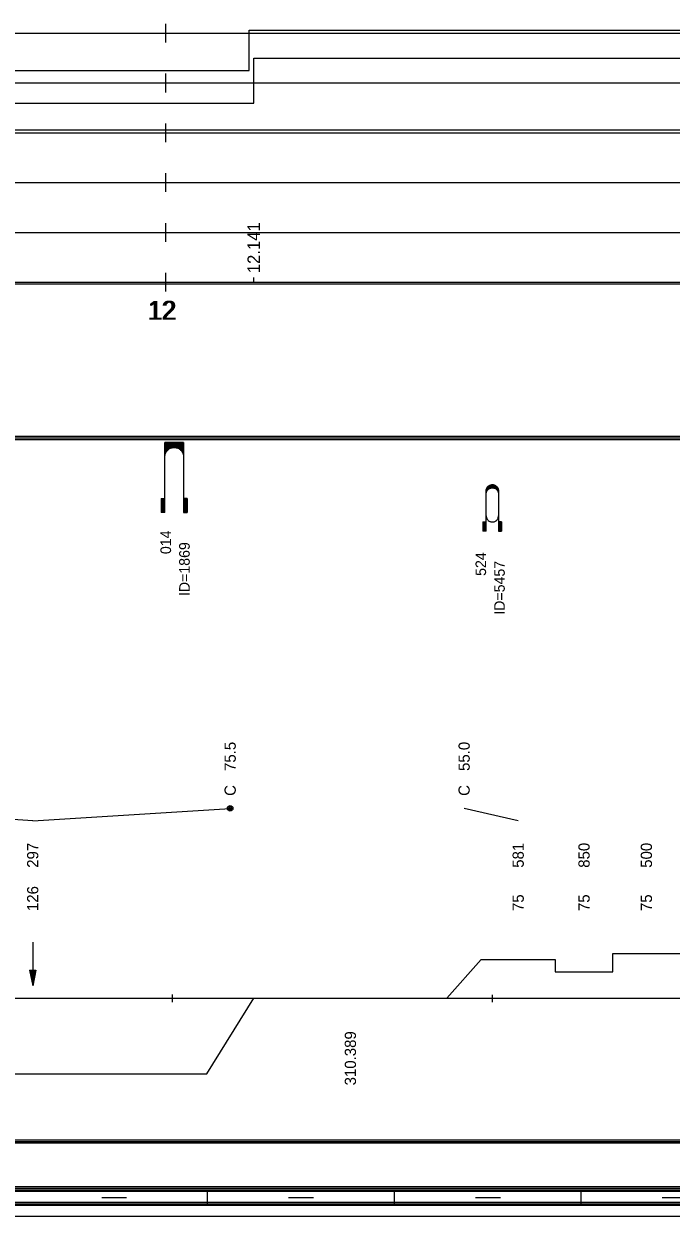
# Model space of a CAD drawing. Extents: x 2 to 10148, y 0 to 380.
# Drawn here: x 1475.5 to 1579.4, y 0 to 191.5 of the extents above; entities that cross this region are included whole.
import ezdxf

# ---------------------------------------------------------------- set-up
doc = ezdxf.new("R2010")
doc.units = 0
for name, color, linetype in [('CARA_S_OBJEKTY', 7, 'Continuous'), ('KRIV1_CARA', 7, 'Continuous'), ('KRIV1_TEXT', 7, 'Continuous'), ('OBJEKTY_TEXT', 7, 'Continuous'), ('OBJEKTY_TVAR', 7, 'Continuous'), ('RAM', 7, 'Continuous'), ('RYCHL_A', 7, 'Continuous'), ('RYCHL_B', 7, 'Continuous'), ('RYCHL_C', 7, 'Continuous'), ('RYCHL_RASTR', 7, 'Continuous'), ('RYCHL_STAN', 7, 'Continuous'), ('STAN_CARA', 7, 'Continuous'), ('STANIC_ZMEN_V', 7, 'Continuous')]:
    doc.layers.add(name, color=color, linetype=linetype)

msp = doc.modelspace()

# ---------------------------------------------------------------- linework, layer by layer
for p, q in [((1499.33, 35.58), (1499.33, 34.39)), ((1550.68, 35.56), (1550.68, 34.37))]:
    msp.add_line(p, q)
at = {"layer": 'CARA_S_OBJEKTY'}
for p, q in [((1245.39, 125.25), (1850.83, 125.25)), ((1245.39, 125), (1850.83, 125)), ((1245.39, 124.75), (1850.83, 124.75))]:
    msp.add_line(p, q, dxfattribs=at)
at = {"layer": 'KRIV1_CARA'}
for p, q in [((1570.07, 39.24), (1570.07, 42.2)), ((1570.07, 42.2), (1580.8, 42.2)), ((1543.43, 35), (1548.93, 41.2)), ((1548.93, 41.2), (1560.78, 41.2)), ((1560.78, 41.2), (1560.78, 39.24)), ((1560.78, 39.24), (1570.07, 39.24)), ((1245.39, 35), (1850.83, 35)), ((1504.85, 22.86), (1512.4, 35)), ((1449, 22.86), (1504.85, 22.86))]:
    msp.add_line(p, q, dxfattribs=at)
at = {"layer": 'KRIV1_TEXT'}
for p, q in [((1476.92, 63.5), (1444.03, 65.5)), ((1476.92, 63.5), (1508.62, 65.5)), ((1554.86, 63.5), (1546.18, 65.5)), ((1476.92, 44), (1476.92, 42.2)), ((1476.92, 42.2), (1476.92, 40)), ((1476.42, 39.5), (1476.92, 37)), ((1476.42, 39.5), (1477.42, 39.5)), ((1476.52, 39.5), (1476.92, 37.5)), ((1476.62, 39.5), (1476.92, 38)), ((1476.72, 39.5), (1476.92, 38.5)), ((1476.82, 39.5), (1476.92, 39)), ((1476.92, 40), (1476.92, 37)), ((1477.42, 39.5), (1476.92, 37)), ((1477.32, 39.5), (1476.92, 37.5)), ((1477.22, 39.5), (1476.92, 38)), ((1477.12, 39.5), (1476.92, 38.5)), ((1477.02, 39.5), (1476.92, 39)), ((1476.92, 39.5), (1476.92, 39.5)), ((1476.92, 39.5), (1476.92, 39.5))]:
    msp.add_line(p, q, dxfattribs=at)
for radius in [0.45, 0.3, 0.15]:
    msp.add_circle((1508.62, 65.5), radius, dxfattribs=at)
at = {"layer": 'OBJEKTY_TVAR'}
for p, q in [((1498.13, 113), (1498.13, 124.25)), ((1501.13, 124.25), (1498.13, 124.25)), ((1498.13, 124.17), (1501.13, 124.17)), ((1498.13, 124.1), (1501.13, 124.1)), ((1498.13, 124.02), (1501.13, 124.02)), ((1498.13, 123.95), (1501.13, 123.95)), ((1498.13, 123.87), (1501.13, 123.87)), ((1498.13, 123.8), (1501.13, 123.8)), ((1498.13, 123.72), (1501.13, 123.72)), ((1498.13, 123.65), (1501.13, 123.65)), ((1498.13, 123.57), (1501.13, 123.57)), ((1498.13, 123.5), (1501.13, 123.5)), ((1498.13, 123.42), (1499.29, 123.42)), ((1498.13, 123.35), (1499.05, 123.35)), ((1498.13, 123.27), (1498.9, 123.27)), ((1498.13, 123.2), (1498.78, 123.2)), ((1498.13, 123.12), (1498.68, 123.12)), ((1498.13, 123.05), (1498.59, 123.05)), ((1498.13, 122.97), (1498.52, 122.97)), ((1498.13, 122.9), (1498.46, 122.9)), ((1498.13, 122.82), (1498.4, 122.82)), ((1498.13, 122.75), (1498.35, 122.75)), ((1498.13, 122.67), (1498.31, 122.67)), ((1498.13, 122.6), (1498.27, 122.6)), ((1498.21, 122.46), (1498.28, 122.61)), ((1498.28, 122.61), (1498.35, 122.75)), ((1498.35, 122.75), (1498.46, 122.9)), ((1498.46, 122.9), (1498.59, 123.05)), ((1498.59, 123.05), (1498.67, 123.12)), ((1498.67, 123.12), (1498.77, 123.19)), ((1498.77, 123.19), (1498.9, 123.27)), ((1498.9, 123.27), (1499.05, 123.35)), ((1499.05, 123.35), (1499.29, 123.42)), ((1499.29, 123.42), (1499.5, 123.46)), ((1499.5, 123.46), (1499.75, 123.46)), ((1499.75, 123.46), (1499.89, 123.44)), ((1499.89, 123.44), (1499.97, 123.42)), ((1499.97, 123.42), (1501.13, 123.42)), ((1499.97, 123.42), (1500.21, 123.35)), ((1500.21, 123.35), (1501.13, 123.35)), ((1500.21, 123.35), (1500.36, 123.27)), ((1500.36, 123.27), (1501.13, 123.27)), ((1500.36, 123.27), (1500.48, 123.2)), ((1500.48, 123.2), (1501.13, 123.2)), ((1500.48, 123.2), (1500.58, 123.12)), ((1500.58, 123.12), (1501.13, 123.12)), ((1500.58, 123.12), (1500.67, 123.05)), ((1500.67, 123.05), (1501.13, 123.05)), ((1500.67, 123.05), (1500.74, 122.97)), ((1500.74, 122.97), (1501.13, 122.97)), ((1500.74, 122.97), (1500.8, 122.9)), ((1500.8, 122.9), (1501.12, 122.9)), ((1500.8, 122.9), (1500.86, 122.82)), ((1500.86, 122.82), (1501.13, 122.82)), ((1500.86, 122.82), (1500.95, 122.67)), ((1500.91, 122.75), (1501.13, 122.75)), ((1500.95, 122.67), (1501.13, 122.67)), ((1500.95, 122.67), (1501.02, 122.52)), ((1500.99, 122.6), (1501.13, 122.6)), ((1501.13, 124.25), (1501.13, 113)), ((1498.13, 122.52), (1498.24, 122.52)), ((1498.13, 122.45), (1498.21, 122.45)), ((1498.13, 122.37), (1498.19, 122.37)), ((1498.13, 122.3), (1498.17, 122.3)), ((1498.13, 122.22), (1498.15, 122.22)), ((1498.13, 122.15), (1498.14, 122.15)), ((1498.13, 121.97), (1498.14, 122.11)), ((1498.14, 122.11), (1498.16, 122.28)), ((1498.16, 122.28), (1498.21, 122.46)), ((1501.02, 122.52), (1501.13, 122.52)), ((1501.02, 122.52), (1501.07, 122.37)), ((1501.05, 122.45), (1501.13, 122.45)), ((1501.07, 122.37), (1501.13, 122.37)), ((1501.07, 122.37), (1501.11, 122.22)), ((1501.09, 122.3), (1501.13, 122.3)), ((1501.11, 122.22), (1501.13, 122.22)), ((1501.11, 122.22), (1501.13, 121.97)), ((1501.12, 122.15), (1501.13, 122.15)), ((1549.76, 116.81), (1549.82, 116.95)), ((1549.77, 116.85), (1550.22, 116.85)), ((1549.79, 116.9), (1550.33, 116.9)), ((1549.82, 116.95), (1549.88, 117.06)), ((1549.82, 116.95), (1550.48, 116.95)), ((1549.84, 117), (1551.58, 117)), ((1549.87, 117.05), (1551.55, 117.05)), ((1549.88, 117.06), (1549.97, 117.18)), ((1549.91, 117.1), (1551.51, 117.1)), ((1549.95, 117.15), (1551.47, 117.15)), ((1549.97, 117.18), (1550.06, 117.26)), ((1550, 117.2), (1551.42, 117.2)), ((1550.05, 117.25), (1551.37, 117.25)), ((1550.06, 117.26), (1550.19, 117.35)), ((1550.06, 116.74), (1550.19, 116.83)), ((1550.11, 117.3), (1551.31, 117.3)), ((1550.18, 117.35), (1551.24, 117.35)), ((1550.19, 117.35), (1550.32, 117.42)), ((1550.19, 116.83), (1550.32, 116.9)), ((1550.27, 117.4), (1551.15, 117.4)), ((1550.32, 117.42), (1550.35, 117.43)), ((1550.32, 116.9), (1550.35, 116.91)), ((1550.35, 117.43), (1550.47, 117.47)), ((1550.35, 116.91), (1550.47, 116.95)), ((1550.4, 117.45), (1551.02, 117.45)), ((1550.47, 117.47), (1550.61, 117.49)), ((1550.47, 116.95), (1550.61, 116.97)), ((1550.61, 117.49), (1550.72, 117.5)), ((1550.61, 116.97), (1550.72, 116.98)), ((1550.72, 117.5), (1550.85, 117.49)), ((1550.72, 116.98), (1550.85, 116.97)), ((1550.85, 117.49), (1550.98, 117.46)), ((1550.85, 116.97), (1550.98, 116.94)), ((1550.94, 116.95), (1551.6, 116.95)), ((1550.98, 117.46), (1551.09, 117.43)), ((1550.98, 116.94), (1551.09, 116.9)), ((1551.09, 117.43), (1551.2, 117.37)), ((1551.09, 116.9), (1551.2, 116.85)), ((1551.09, 116.9), (1551.63, 116.9)), ((1551.2, 117.37), (1551.27, 117.32)), ((1551.2, 116.85), (1551.65, 116.85)), ((1551.2, 116.85), (1551.27, 116.8)), ((1551.27, 117.32), (1551.42, 117.21)), ((1551.42, 117.21), (1551.5, 117.11)), ((1551.5, 117.11), (1551.59, 116.98)), ((1551.59, 116.98), (1551.63, 116.89)), ((1551.63, 116.89), (1551.67, 116.77)), ((1497.53, 115.25), (1498.13, 115.25)), ((1497.53, 115.25), (1497.53, 113)), ((1497.6, 115.25), (1497.6, 113)), ((1497.68, 115.25), (1497.68, 113)), ((1497.75, 115.25), (1497.75, 113)), ((1497.83, 115.25), (1497.83, 113)), ((1497.9, 115.25), (1497.9, 113)), ((1497.98, 115.25), (1497.98, 113)), ((1498.05, 115.25), (1498.05, 113)), ((1501.73, 115.25), (1501.13, 115.25)), ((1501.21, 115.25), (1501.21, 113)), ((1501.28, 115.25), (1501.28, 113)), ((1501.36, 115.25), (1501.36, 113)), ((1501.43, 115.25), (1501.43, 113)), ((1501.51, 115.25), (1501.51, 113)), ((1501.58, 115.25), (1501.58, 113)), ((1501.66, 115.25), (1501.66, 113)), ((1501.73, 115.25), (1501.73, 113)), ((1549.71, 116.5), (1549.72, 116.65)), ((1549.71, 116.55), (1549.89, 116.55)), ((1549.71, 110), (1549.71, 116.5)), ((1549.71, 116.5), (1549.86, 116.5)), ((1549.71, 116.45), (1549.83, 116.45)), ((1549.71, 116.4), (1549.8, 116.4)), ((1549.71, 116.35), (1549.78, 116.35)), ((1549.71, 116.3), (1549.76, 116.3)), ((1549.71, 116.25), (1549.75, 116.25)), ((1549.71, 116.2), (1549.74, 116.2)), ((1549.71, 116.15), (1549.73, 116.15)), ((1549.71, 115.98), (1549.72, 116.13)), ((1549.71, 116.1), (1549.72, 116.1)), ((1549.72, 116.65), (1549.76, 116.81)), ((1549.72, 116.65), (1549.97, 116.65)), ((1549.72, 116.6), (1549.93, 116.6)), ((1549.72, 116.13), (1549.76, 116.28)), ((1549.73, 116.7), (1550.02, 116.7)), ((1549.74, 116.75), (1550.08, 116.75)), ((1549.76, 116.8), (1550.14, 116.8)), ((1549.76, 116.28), (1549.82, 116.43)), ((1549.82, 116.43), (1549.88, 116.53)), ((1549.88, 116.53), (1549.97, 116.65)), ((1549.97, 116.65), (1550.06, 116.74)), ((1551.27, 116.8), (1551.42, 116.68)), ((1551.28, 116.8), (1551.66, 116.8)), ((1551.34, 116.75), (1551.68, 116.75)), ((1551.4, 116.7), (1551.69, 116.7)), ((1551.42, 116.68), (1551.5, 116.59)), ((1551.45, 116.65), (1551.7, 116.65)), ((1551.49, 116.6), (1551.7, 116.6)), ((1551.5, 116.59), (1551.59, 116.46)), ((1551.53, 116.55), (1551.71, 116.55)), ((1551.56, 116.5), (1551.71, 116.5)), ((1551.59, 116.46), (1551.63, 116.37)), ((1551.59, 116.45), (1551.71, 116.45)), ((1551.62, 116.4), (1551.71, 116.4)), ((1551.63, 116.37), (1551.67, 116.24)), ((1551.64, 116.35), (1551.71, 116.35)), ((1551.66, 116.3), (1551.71, 116.3)), ((1551.67, 116.77), (1551.7, 116.65)), ((1551.67, 116.25), (1551.71, 116.25)), ((1551.67, 116.24), (1551.7, 116.13)), ((1551.68, 116.2), (1551.71, 116.2)), ((1551.69, 116.15), (1551.71, 116.15)), ((1551.7, 116.65), (1551.71, 116.56)), ((1551.7, 116.13), (1551.71, 116.03)), ((1551.7, 116.1), (1551.71, 116.1)), ((1551.71, 116.56), (1551.71, 116.5)), ((1551.71, 116.5), (1551.71, 110)), ((1551.71, 116.03), (1551.71, 115.98)), ((1498.13, 113), (1497.53, 113)), ((1501.13, 113), (1501.73, 113)), ((1549.21, 111.5), (1549.71, 111.5)), ((1549.21, 111.5), (1549.21, 110)), ((1549.26, 111.5), (1549.26, 110)), ((1549.31, 111.5), (1549.31, 110)), ((1549.36, 111.5), (1549.36, 110)), ((1549.41, 111.5), (1549.41, 110)), ((1549.46, 111.5), (1549.46, 110)), ((1549.51, 111.5), (1549.51, 110)), ((1549.56, 111.5), (1549.56, 110)), ((1549.61, 111.5), (1549.61, 110)), ((1549.66, 111.5), (1549.66, 110)), ((1549.71, 112.5), (1549.72, 112.35)), ((1549.72, 112.35), (1549.76, 112.2)), ((1549.76, 112.2), (1549.82, 112.05)), ((1549.82, 112.05), (1549.88, 111.95)), ((1549.88, 111.95), (1549.97, 111.83)), ((1549.97, 111.83), (1550.06, 111.74)), ((1550.06, 111.74), (1550.19, 111.65)), ((1550.19, 111.65), (1550.32, 111.58)), ((1550.32, 111.58), (1550.35, 111.57)), ((1550.35, 111.57), (1550.47, 111.53)), ((1550.47, 111.53), (1550.61, 111.51)), ((1550.61, 111.51), (1550.72, 111.5)), ((1550.72, 111.5), (1550.85, 111.51)), ((1550.85, 111.51), (1550.98, 111.54)), ((1550.98, 111.54), (1551.09, 111.58)), ((1551.09, 111.58), (1551.2, 111.63)), ((1551.2, 111.63), (1551.27, 111.68)), ((1551.27, 111.68), (1551.42, 111.8)), ((1551.42, 111.8), (1551.5, 111.9)), ((1551.5, 111.9), (1551.59, 112.02)), ((1551.59, 112.02), (1551.63, 112.11)), ((1551.63, 112.11), (1551.67, 112.24)), ((1551.67, 112.24), (1551.7, 112.35)), ((1551.7, 112.35), (1551.71, 112.45)), ((1551.71, 112.45), (1551.71, 112.5)), ((1552.21, 111.5), (1551.71, 111.5)), ((1551.76, 111.5), (1551.76, 110)), ((1551.81, 111.5), (1551.81, 110)), ((1551.86, 111.5), (1551.86, 110)), ((1551.91, 111.5), (1551.91, 110)), ((1551.96, 111.5), (1551.96, 110)), ((1552.01, 111.5), (1552.01, 110)), ((1552.06, 111.5), (1552.06, 110)), ((1552.11, 111.5), (1552.11, 110)), ((1552.16, 111.5), (1552.16, 110)), ((1552.21, 111.5), (1552.21, 110)), ((1549.71, 110), (1549.21, 110)), ((1551.71, 110), (1552.21, 110))]:
    msp.add_line(p, q, dxfattribs=at)
at = {"layer": 'RAM'}
for p, q in [((1245.39, 4.75), (1850.83, 4.75)), ((1245.39, 4.5), (1850.83, 4.5)), ((1245.39, 4.25), (1850.83, 4.25)), ((1245.39, 4), (1850.83, 4)), ((1505, 2), (1505, 4)), ((1535, 2), (1535, 4)), ((1565, 2), (1565, 4)), ((1245.39, 2.25), (1850.83, 2.25)), ((1245.39, 2), (1850.83, 2)), ((1488, 3), (1492, 3)), ((1518, 3), (1522, 3)), ((1548, 3), (1552, 3)), ((1578, 3), (1582, 3)), ((1245.39, 1.75), (1850.83, 1.75)), ((1245.39, 0), (1850.83, 0))]:
    msp.add_line(p, q, dxfattribs=at)
at = {"layer": 'RYCHL_A'}
msp.add_line((1403.28, 174.5), (1850.83, 174.5), dxfattribs=at)
at = {"layer": 'RYCHL_B'}
for p, q in [((1512.4, 178.75), (1512.4, 186)), ((1512.4, 186), (1850.83, 186)), ((1245.69, 178.75), (1512.4, 178.75))]:
    msp.add_line(p, q, dxfattribs=at)
at = {"layer": 'RYCHL_C'}
for p, q in [((1511.67, 184), (1511.65, 190.5)), ((1511.65, 190.5), (1851.98, 190.5)), ((1089.27, 184), (1511.67, 184))]:
    msp.add_line(p, q, dxfattribs=at)
at = {"layer": 'RYCHL_RASTR'}
for p, q in [((1498.28, 188.5), (1498.28, 191.5)), ((1245.39, 190), (1854.26, 190)), ((1245.39, 182), (1853.57, 182)), ((1498.28, 180.5), (1498.28, 183.5)), ((1498.28, 172.5), (1498.28, 175.5)), ((1245.39, 174), (1854.63, 174)), ((1498.28, 164.5), (1498.28, 167.5)), ((1245.39, 166), (1853.77, 166)), ((1498.28, 156.5), (1498.28, 159.5)), ((1245.39, 158), (1853.78, 158)), ((1498.28, 148.5), (1498.28, 151.5)), ((1245.39, 150), (1850.83, 150)), ((1245.39, 149.75), (1850.83, 149.75))]:
    msp.add_line(p, q, dxfattribs=at)
at = {"layer": 'STAN_CARA'}
for p, q in [((1299.78, 12.25), (1796.78, 12.25)), ((1299.78, 12), (1796.78, 12)), ((1299.78, 12), (1796.78, 12)), ((1299.78, 11.75), (1796.78, 11.75))]:
    msp.add_line(p, q, dxfattribs=at)
at = {"layer": 'STANIC_ZMEN_V'}
msp.add_line((1512.4, 150), (1512.4, 150.75), dxfattribs=at)

# ---------------------------------------------------------------- texts
at = {"layer": 'KRIV1_TEXT'}
for s, p in [('75.5', (1509.52, 71.5)), ('55.0', (1547.08, 71.5)), ('C', (1509.52, 67.5)), ('C', (1547.08, 67.5)), ('297', (1477.82, 55.95)), ('581', (1555.76, 55.95)), ('850', (1566.33, 55.95)), ('500', (1576.34, 55.95)), ('126', (1477.82, 49)), ('75', (1555.76, 49)), ('75', (1566.33, 49)), ('75', (1576.34, 49)), ('310.389', (1528.82, 21))]:
    msp.add_text(s, height=1.8, rotation=90, dxfattribs=at).set_placement(p)
at = {"layer": 'OBJEKTY_TEXT'}
for s, p in [('014', (1499.13, 106.33)), ('ID=1869', (1502.13, 99.59)), ('524', (1549.71, 102.83)), ('ID=5457', (1552.71, 96.59))]:
    msp.add_text(s, height=1.7, rotation=90, dxfattribs=at).set_placement(p)
at = {"layer": 'RYCHL_STAN'}
for p in [(1495.34, 144), (1495.59, 144)]:
    msp.add_text('12', height=3, dxfattribs=at).set_placement(p)
at = {"layer": 'STANIC_ZMEN_V'}
msp.add_text('12.141', height=2, rotation=90, dxfattribs=at).set_placement((1513.4, 151.45))

doc.saveas('drawing.dxf')
